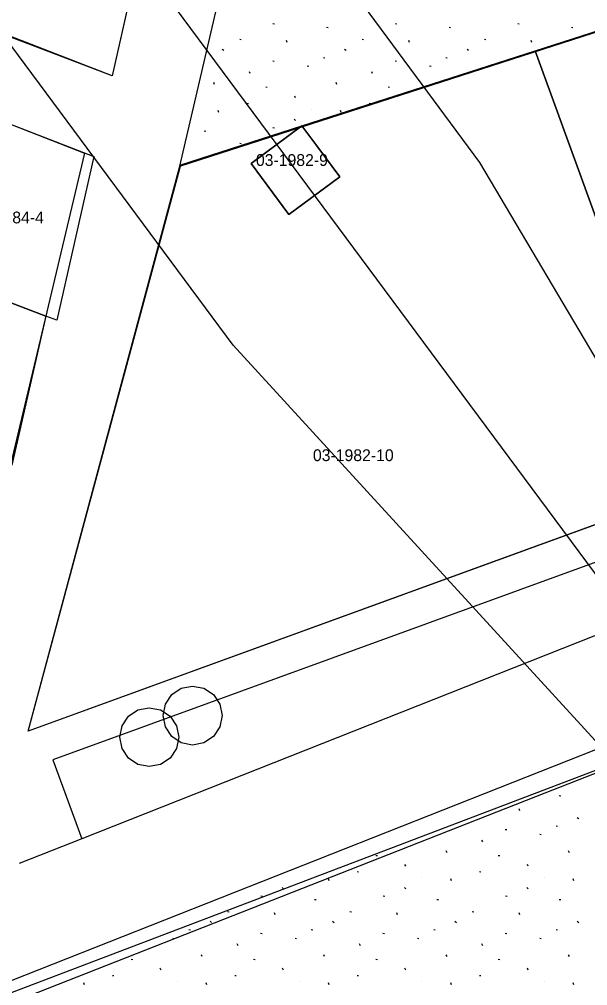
# Model space of a CAD drawing. Extents: x 413946 to 415528, y 4453939 to 4454944.
# Drawn here: x 414023.8 to 414071.9, y 4454810.9 to 4454892.9 of the extents above; entities that cross this region are included whole.
import ezdxf

# ---------------------------------------------------------------- set-up
doc = ezdxf.new("R2010")
doc.units = 0
for name, color, linetype in [('0_KADASTRO', 7, 'Continuous'), ('HAT_ENERJI_NAKIL_HAT', 7, 'Continuous'), ('KST_ENERJI_NAKIL_HAT', 7, 'Continuous'), ('Level 27', 7, 'Continuous'), ('Level 28', 7, 'Continuous'), ('Level 29', 7, 'Continuous'), ('Level 41', 7, 'Continuous'), ('Level 54', 7, 'Continuous'), ('Level 62', 7, 'Continuous'), ('SNR_FONKSIYON', 7, 'Continuous')]:
    doc.layers.add(name, color=color, linetype=linetype)

msp = doc.modelspace()

# ---------------------------------------------------------------- linework, layer by layer
at = {"layer": '0_KADASTRO'}
for points in [[(414020.97, 4454892.22), (414021.31, 4454893.14), (414023.89, 4454900.29), (414026, 4454905.75), (414030.78, 4454921.5), (414033.2, 4454920.77), (414038.65, 4454919.17), (414037.64, 4454914.76), (414031.62, 4454888.06), (414022.41, 4454891.66)], [(414067.47, 4454890.2), (414112.978, 4454904.868), (414125.885, 4454869.418), (414080.98, 4454853.07)], [(414024.52, 4454832.51), (414037.44, 4454880.52), (414047.72, 4454883.84), (414043.4, 4454880.63), (414046.6, 4454876.31), (414050.93, 4454879.51), (414048.98, 4454882.14), (414047.72, 4454883.84), (414067.47, 4454890.2), (414080.98, 4454853.07)], [(414017.66, 4454870.9), (414018.7, 4454873.47), (414022.51, 4454884.18), (414030.08, 4454881.22), (414026.94, 4454867.35), (414026.009, 4454867.706)], [(414043.4, 4454880.63), (414047.72, 4454883.84), (414048.98, 4454882.14), (414050.93, 4454879.51), (414046.6, 4454876.31)], [(414005.69, 4454860.71), (414009.57, 4454869.91), (414010.56, 4454873.54), (414017.66, 4454870.9), (414026.009, 4454867.706), (414023.14, 4454855.05)], [(414008.02, 4454803.57), (414068.33, 4454827.27), (414083.68, 4454833.3), (414088.17, 4454830.9), (414106.37, 4454805.76), (414106.62, 4454802.77), (414104.47, 4454806.16), (414101.1, 4454804.02), (414103.24, 4454800.64), (414106.62, 4454802.77), (414103.28, 4454796.68), (414079.29, 4454753.02)]]:
    msp.add_lwpolyline(points, close=True, dxfattribs=at)
at = {"layer": 'HAT_ENERJI_NAKIL_HAT'}
msp.add_lwpolyline([(414658.516, 4453939.478), (414647.224, 4454070.234), (413999.883, 4454943.957)], dxfattribs=at)
at = {"layer": 'KST_ENERJI_NAKIL_HAT'}
for p, q in [((414041.874, 4454865.239), (413983.573, 4454943.957)), ((414036.749, 4454915.966), (414062.768, 4454880.714)), ((414062.768, 4454880.714), (414107.065, 4454805.782)), ((414100.636, 4454801.021), (414041.874, 4454865.239))]:
    msp.add_line(p, q, dxfattribs=at)
at = {"layer": 'Level 27'}
for p, q in [((414038.65, 4454919.17), (414031.62, 4454888.06)), ((414031.62, 4454888.06), (414020.773, 4454892.194)), ((414022.51, 4454884.18), (414029.299, 4454881.525))]:
    msp.add_line(p, q, dxfattribs=at)
at = {"layer": 'Level 28'}
for p, q in [((414037.376, 4454880.414), (414044.828, 4454912.566)), ((414235.366, 4454909.281), (414024.523, 4454832.51)), ((414024.523, 4454832.51), (414037.376, 4454880.414)), ((414005.358, 4454803.615), (414085.768, 4454834.218))]:
    msp.add_line(p, q, dxfattribs=at)
at = {"layer": 'Level 29'}
msp.add_line((414029.299, 4454881.525), (414023.017, 4454855.088), dxfattribs=at)
at = {"layer": 'Level 41'}
for p, q in [((414045.262, 4454892.493), (414045.388, 4454892.469)), ((414045.262, 4454892.493), (414045.388, 4454892.469)), ((414055.63, 4454892.493), (414055.756, 4454892.469)), ((414055.63, 4454892.493), (414055.756, 4454892.469)), ((414065.998, 4454892.493), (414066.124, 4454892.469)), ((414065.998, 4454892.493), (414066.124, 4454892.469)), ((414049.81, 4454892.199), (414049.936, 4454892.176)), ((414049.81, 4454892.199), (414049.936, 4454892.176)), ((414060.178, 4454892.199), (414060.304, 4454892.176)), ((414060.178, 4454892.199), (414060.304, 4454892.176)), ((414070.546, 4454892.199), (414070.672, 4454892.176)), ((414070.546, 4454892.199), (414070.672, 4454892.176)), ((414042.442, 4454891.175), (414042.567, 4454891.15)), ((414042.442, 4454891.175), (414042.567, 4454891.15)), ((414046.475, 4454890.895), (414046.41, 4454891.058)), ((414046.475, 4454890.895), (414046.41, 4454891.058)), ((414052.81, 4454891.175), (414052.935, 4454891.15)), ((414052.81, 4454891.175), (414052.935, 4454891.15)), ((414056.843, 4454890.895), (414056.778, 4454891.058)), ((414056.843, 4454890.895), (414056.778, 4454891.058)), ((414063.178, 4454891.175), (414063.303, 4454891.15)), ((414063.178, 4454891.175), (414063.303, 4454891.15)), ((414067.211, 4454890.895), (414067.146, 4454891.058)), ((414067.211, 4454890.895), (414067.146, 4454891.058)), ((414040.967, 4454890.337), (414041.094, 4454890.238)), ((414040.967, 4454890.337), (414041.094, 4454890.238)), ((414051.335, 4454890.337), (414051.462, 4454890.238)), ((414051.335, 4454890.337), (414051.462, 4454890.238)), ((414061.703, 4454890.337), (414061.83, 4454890.238)), ((414061.703, 4454890.337), (414061.83, 4454890.238)), ((414045.235, 4454889.327), (414045.361, 4454889.304)), ((414045.235, 4454889.327), (414045.361, 4454889.304)), ((414049.54, 4454889.631), (414049.666, 4454889.608)), ((414049.54, 4454889.631), (414049.666, 4454889.608)), ((414055.603, 4454889.327), (414055.729, 4454889.304)), ((414055.603, 4454889.327), (414055.729, 4454889.304)), ((414059.908, 4454889.631), (414060.034, 4454889.608)), ((414059.908, 4454889.631), (414060.034, 4454889.608)), ((414043.332, 4454888.258), (414043.266, 4454888.421)), ((414043.332, 4454888.258), (414043.266, 4454888.421)), ((414048.164, 4454888.918), (414048.29, 4454888.893)), ((414048.164, 4454888.918), (414048.29, 4454888.893)), ((414053.7, 4454888.258), (414053.634, 4454888.421)), ((414053.7, 4454888.258), (414053.634, 4454888.421)), ((414058.532, 4454888.918), (414058.658, 4454888.893)), ((414058.532, 4454888.918), (414058.658, 4454888.893)), ((414040.301, 4454887.344), (414040.236, 4454887.507)), ((414040.301, 4454887.344), (414040.236, 4454887.507)), ((414050.669, 4454887.344), (414050.604, 4454887.507)), ((414050.669, 4454887.344), (414050.604, 4454887.507)), ((414044.65, 4454887.123), (414044.777, 4454887.1)), ((414044.65, 4454887.123), (414044.777, 4454887.1)), ((414055.018, 4454887.123), (414055.145, 4454887.1)), ((414055.018, 4454887.123), (414055.145, 4454887.1)), ((414047.173, 4454886.195), (414047.109, 4454886.356)), ((414047.173, 4454886.195), (414047.109, 4454886.356)), ((414040.682, 4454884.961), (414040.617, 4454885.123)), ((414040.682, 4454884.961), (414040.617, 4454885.123)), ((414043.047, 4454885.756), (414043.173, 4454885.731)), ((414043.047, 4454885.756), (414043.173, 4454885.731)), ((414048.531, 4454885.231), (414048.539, 4454885.229)), ((414048.531, 4454885.231), (414048.539, 4454885.229)), ((414051.05, 4454884.961), (414050.985, 4454885.123)), ((414051.05, 4454884.961), (414050.985, 4454885.123)), ((414053.415, 4454885.756), (414053.541, 4454885.731)), ((414053.415, 4454885.756), (414053.541, 4454885.731)), ((414047.056, 4454884.392), (414047.183, 4454884.294)), ((414047.056, 4454884.392), (414047.183, 4454884.294)), ((414045.262, 4454883.687), (414045.388, 4454883.663)), ((414045.262, 4454883.687), (414045.388, 4454883.663)), ((414039.442, 4454883.393), (414039.568, 4454883.37)), ((414039.442, 4454883.393), (414039.568, 4454883.37)), ((414042.442, 4454882.369), (414042.567, 4454882.344)), ((414042.442, 4454882.369), (414042.567, 4454882.344)), ((414069.517, 4454827.055), (414069.643, 4454827.032)), ((414069.517, 4454827.055), (414069.643, 4454827.032)), ((414066.182, 4454825.752), (414066.117, 4454825.914)), ((414066.182, 4454825.752), (414066.117, 4454825.914)), ((414069.247, 4454824.487), (414069.373, 4454824.464)), ((414069.247, 4454824.487), (414069.373, 4454824.464)), ((414071.042, 4454825.193), (414071.169, 4454825.094)), ((414071.042, 4454825.193), (414071.169, 4454825.094)), ((414064.942, 4454824.183), (414065.068, 4454824.16)), ((414064.942, 4454824.183), (414065.068, 4454824.16)), ((414067.871, 4454823.774), (414067.998, 4454823.749)), ((414067.871, 4454823.774), (414067.998, 4454823.749)), ((414063.039, 4454823.114), (414062.973, 4454823.277)), ((414063.039, 4454823.114), (414062.973, 4454823.277)), ((414053.99, 4454821.979), (414054.116, 4454821.956)), ((414053.99, 4454821.979), (414054.116, 4454821.956)), ((414060.008, 4454822.2), (414059.943, 4454822.363)), ((414060.008, 4454822.2), (414059.943, 4454822.363)), ((414064.358, 4454821.979), (414064.484, 4454821.956)), ((414064.358, 4454821.979), (414064.484, 4454821.956)), ((414070.376, 4454822.2), (414070.311, 4454822.363)), ((414070.376, 4454822.2), (414070.311, 4454822.363)), ((414056.512, 4454821.051), (414056.448, 4454821.212)), ((414056.512, 4454821.051), (414056.448, 4454821.212)), ((414066.88, 4454821.051), (414066.816, 4454821.212)), ((414066.88, 4454821.051), (414066.816, 4454821.212)), ((414052.386, 4454820.612), (414052.512, 4454820.587)), ((414052.386, 4454820.612), (414052.512, 4454820.587)), ((414062.754, 4454820.612), (414062.88, 4454820.587)), ((414062.754, 4454820.612), (414062.88, 4454820.587)), ((414050.021, 4454819.817), (414049.956, 4454819.98)), ((414050.021, 4454819.817), (414049.956, 4454819.98)), ((414057.87, 4454820.087), (414057.878, 4454820.085)), ((414057.87, 4454820.087), (414057.878, 4454820.085)), ((414060.389, 4454819.817), (414060.324, 4454819.98)), ((414060.389, 4454819.817), (414060.324, 4454819.98)), ((414068.238, 4454820.087), (414068.246, 4454820.085)), ((414068.238, 4454820.087), (414068.246, 4454820.085)), ((414070.757, 4454819.817), (414070.692, 4454819.98)), ((414070.757, 4454819.817), (414070.692, 4454819.98)), ((414046.027, 4454819.248), (414046.154, 4454819.15)), ((414046.027, 4454819.248), (414046.154, 4454819.15)), ((414056.395, 4454819.248), (414056.522, 4454819.15)), ((414056.395, 4454819.248), (414056.522, 4454819.15)), ((414066.763, 4454819.248), (414066.89, 4454819.15)), ((414066.763, 4454819.248), (414066.89, 4454819.15)), ((414044.233, 4454818.543), (414044.359, 4454818.519)), ((414044.233, 4454818.543), (414044.359, 4454818.519)), ((414048.781, 4454818.249), (414048.907, 4454818.226)), ((414048.781, 4454818.249), (414048.907, 4454818.226)), ((414054.601, 4454818.543), (414054.727, 4454818.519)), ((414054.601, 4454818.543), (414054.727, 4454818.519)), ((414059.149, 4454818.249), (414059.275, 4454818.226)), ((414059.149, 4454818.249), (414059.275, 4454818.226)), ((414064.969, 4454818.543), (414065.095, 4454818.519)), ((414064.969, 4454818.543), (414065.095, 4454818.519)), ((414069.517, 4454818.249), (414069.643, 4454818.226)), ((414069.517, 4454818.249), (414069.643, 4454818.226)), ((414041.413, 4454817.225), (414041.538, 4454817.2)), ((414041.413, 4454817.225), (414041.538, 4454817.2)), ((414045.446, 4454816.946), (414045.381, 4454817.108)), ((414045.446, 4454816.946), (414045.381, 4454817.108)), ((414051.781, 4454817.225), (414051.906, 4454817.2)), ((414051.781, 4454817.225), (414051.906, 4454817.2)), ((414055.814, 4454816.946), (414055.749, 4454817.108)), ((414055.814, 4454816.946), (414055.749, 4454817.108)), ((414062.149, 4454817.225), (414062.274, 4454817.2)), ((414062.149, 4454817.225), (414062.274, 4454817.2)), ((414066.182, 4454816.946), (414066.117, 4454817.108)), ((414066.182, 4454816.946), (414066.117, 4454817.108)), ((414039.938, 4454816.387), (414040.065, 4454816.288)), ((414039.938, 4454816.387), (414040.065, 4454816.288)), ((414050.306, 4454816.387), (414050.433, 4454816.288)), ((414050.306, 4454816.387), (414050.433, 4454816.288)), ((414060.674, 4454816.387), (414060.801, 4454816.288)), ((414060.674, 4454816.387), (414060.801, 4454816.288)), ((414071.042, 4454816.387), (414071.169, 4454816.288)), ((414071.042, 4454816.387), (414071.169, 4454816.288)), ((414038.143, 4454815.681), (414038.269, 4454815.658)), ((414038.143, 4454815.681), (414038.269, 4454815.658)), ((414048.511, 4454815.681), (414048.637, 4454815.658)), ((414048.511, 4454815.681), (414048.637, 4454815.658)), ((414058.879, 4454815.681), (414059.005, 4454815.658)), ((414058.879, 4454815.681), (414059.005, 4454815.658)), ((414069.247, 4454815.681), (414069.373, 4454815.658)), ((414069.247, 4454815.681), (414069.373, 4454815.658)), ((414036.767, 4454814.968), (414036.894, 4454814.943)), ((414036.767, 4454814.968), (414036.894, 4454814.943)), ((414044.206, 4454815.377), (414044.332, 4454815.354)), ((414044.206, 4454815.377), (414044.332, 4454815.354)), ((414047.135, 4454814.968), (414047.262, 4454814.943)), ((414047.135, 4454814.968), (414047.262, 4454814.943)), ((414054.574, 4454815.377), (414054.7, 4454815.354)), ((414054.574, 4454815.377), (414054.7, 4454815.354)), ((414057.503, 4454814.968), (414057.63, 4454814.943)), ((414057.503, 4454814.968), (414057.63, 4454814.943)), ((414064.942, 4454815.377), (414065.068, 4454815.354)), ((414064.942, 4454815.377), (414065.068, 4454815.354)), ((414067.871, 4454814.968), (414067.998, 4454814.943)), ((414067.871, 4454814.968), (414067.998, 4454814.943)), ((414042.303, 4454814.308), (414042.237, 4454814.471)), ((414042.303, 4454814.308), (414042.237, 4454814.471)), ((414052.671, 4454814.308), (414052.605, 4454814.471)), ((414052.671, 4454814.308), (414052.605, 4454814.471)), ((414063.039, 4454814.308), (414062.973, 4454814.471)), ((414063.039, 4454814.308), (414062.973, 4454814.471)), ((414033.254, 4454813.173), (414033.38, 4454813.15)), ((414033.254, 4454813.173), (414033.38, 4454813.15)), ((414039.272, 4454813.394), (414039.207, 4454813.557)), ((414039.272, 4454813.394), (414039.207, 4454813.557)), ((414043.622, 4454813.173), (414043.748, 4454813.15)), ((414043.622, 4454813.173), (414043.748, 4454813.15)), ((414049.64, 4454813.394), (414049.575, 4454813.557)), ((414049.64, 4454813.394), (414049.575, 4454813.557)), ((414053.99, 4454813.173), (414054.116, 4454813.15)), ((414053.99, 4454813.173), (414054.116, 4454813.15)), ((414060.008, 4454813.394), (414059.943, 4454813.557)), ((414060.008, 4454813.394), (414059.943, 4454813.557)), ((414064.358, 4454813.173), (414064.484, 4454813.15)), ((414064.358, 4454813.173), (414064.484, 4454813.15)), ((414070.376, 4454813.394), (414070.311, 4454813.557)), ((414070.376, 4454813.394), (414070.311, 4454813.557)), ((414035.776, 4454812.245), (414035.712, 4454812.406)), ((414035.776, 4454812.245), (414035.712, 4454812.406)), ((414046.144, 4454812.245), (414046.08, 4454812.406)), ((414046.144, 4454812.245), (414046.08, 4454812.406)), ((414056.512, 4454812.245), (414056.448, 4454812.406)), ((414056.512, 4454812.245), (414056.448, 4454812.406)), ((414066.88, 4454812.245), (414066.816, 4454812.406)), ((414066.88, 4454812.245), (414066.816, 4454812.406)), ((414031.65, 4454811.806), (414031.776, 4454811.781)), ((414031.65, 4454811.806), (414031.776, 4454811.781)), ((414042.018, 4454811.806), (414042.144, 4454811.781)), ((414042.018, 4454811.806), (414042.144, 4454811.781)), ((414052.386, 4454811.806), (414052.512, 4454811.781)), ((414052.386, 4454811.806), (414052.512, 4454811.781)), ((414062.754, 4454811.806), (414062.88, 4454811.781)), ((414062.754, 4454811.806), (414062.88, 4454811.781)), ((414026.766, 4454811.281), (414026.774, 4454811.279)), ((414026.766, 4454811.281), (414026.774, 4454811.279)), ((414029.285, 4454811.011), (414029.22, 4454811.174)), ((414029.285, 4454811.011), (414029.22, 4454811.174)), ((414037.134, 4454811.281), (414037.142, 4454811.279)), ((414037.134, 4454811.281), (414037.142, 4454811.279)), ((414039.653, 4454811.011), (414039.588, 4454811.174)), ((414039.653, 4454811.011), (414039.588, 4454811.174)), ((414047.502, 4454811.281), (414047.51, 4454811.279)), ((414047.502, 4454811.281), (414047.51, 4454811.279)), ((414050.021, 4454811.011), (414049.956, 4454811.174)), ((414050.021, 4454811.011), (414049.956, 4454811.174)), ((414057.87, 4454811.281), (414057.878, 4454811.279)), ((414057.87, 4454811.281), (414057.878, 4454811.279)), ((414060.389, 4454811.011), (414060.324, 4454811.174)), ((414060.389, 4454811.011), (414060.324, 4454811.174)), ((414068.238, 4454811.281), (414068.246, 4454811.279)), ((414068.238, 4454811.281), (414068.246, 4454811.279)), ((414070.757, 4454811.011), (414070.692, 4454811.174)), ((414070.757, 4454811.011), (414070.692, 4454811.174))]:
    msp.add_line(p, q, dxfattribs=at)
at = {"layer": 'Level 54'}
for points in [[(414235.366, 4454909.281), (414024.523, 4454832.51), (414037.376, 4454880.414), (414193.464, 4454930.784), (414203.673, 4454926.215), (414235.49, 4454913.3)], [(414038.65, 4454919.17), (414031.62, 4454888.06), (414020.773, 4454892.194), (414011.73, 4454895.64), (414002.61, 4454899), (414008.44, 4454912.68), (414014.22, 4454926.47), (414022.27, 4454924.05), (414030.78, 4454921.5)], [(414007.46, 4454889.72), (414014.99, 4454886.89), (414018.8, 4454885.66), (414022.51, 4454884.18), (414029.299, 4454881.525), (414023.017, 4454855.088), (414005.69, 4454860.71), (413997.39, 4454864.04), (413996.97, 4454863.1), (413988.28, 4454865.76), (413994.14, 4454879.51), (413999.47, 4454892.62)]]:
    msp.add_lwpolyline(points, close=True, dxfattribs=at)
at = {"layer": 'Level 62'}
for p, q in [((414096.802, 4454850.186), (414029.052, 4454823.393)), ((414100.085, 4454841.806), (414009.342, 4454805.921)), ((414036.682, 4454835.604), (414037.493, 4454836.146)), ((414037.493, 4454836.146), (414038.45, 4454836.336)), ((414038.45, 4454836.336), (414039.407, 4454836.146)), ((414039.407, 4454836.146), (414040.218, 4454835.604)), ((414036.14, 4454834.793), (414036.682, 4454835.604)), ((414040.218, 4454835.604), (414040.76, 4454834.793)), ((414033.009, 4454833.768), (414033.82, 4454834.31)), ((414033.82, 4454834.31), (414034.777, 4454834.5)), ((414034.777, 4454834.5), (414035.734, 4454834.31)), ((414035.734, 4454834.31), (414036.545, 4454833.768)), ((414035.95, 4454833.836), (414036.14, 4454834.793)), ((414040.76, 4454834.793), (414040.95, 4454833.836)), ((414032.467, 4454832.957), (414033.009, 4454833.768)), ((414036.14, 4454832.88), (414035.95, 4454833.836)), ((414036.545, 4454833.768), (414037.087, 4454832.957)), ((414040.95, 4454833.836), (414040.76, 4454832.88)), ((414032.277, 4454832), (414032.467, 4454832.957)), ((414036.682, 4454832.069), (414036.14, 4454832.88)), ((414037.087, 4454832.957), (414037.277, 4454832)), ((414040.76, 4454832.88), (414040.218, 4454832.069)), ((414032.467, 4454831.043), (414032.277, 4454832)), ((414037.493, 4454831.527), (414036.682, 4454832.069)), ((414037.277, 4454832), (414037.087, 4454831.043)), ((414040.218, 4454832.069), (414039.407, 4454831.527)), ((414033.009, 4454830.232), (414032.467, 4454831.043)), ((414037.087, 4454831.043), (414036.545, 4454830.232)), ((414038.45, 4454831.336), (414037.493, 4454831.527)), ((414039.407, 4454831.527), (414038.45, 4454831.336)), ((414033.82, 4454829.69), (414033.009, 4454830.232)), ((414036.545, 4454830.232), (414035.734, 4454829.69)), ((414026.617, 4454830.08), (414029.052, 4454823.393)), ((414034.777, 4454829.5), (414033.82, 4454829.69)), ((414035.734, 4454829.69), (414034.777, 4454829.5)), ((414029.052, 4454823.393), (414023.766, 4454821.303))]:
    msp.add_line(p, q, dxfattribs=at)
msp.add_lwpolyline([(414129.599, 4454867.578), (414026.617, 4454830.08)], dxfattribs=at)
at = {"layer": 'SNR_FONKSIYON'}
msp.add_line((414037.376, 4454880.414), (414193.464, 4454930.784), dxfattribs=at)

# ---------------------------------------------------------------- texts
at = {"layer": '0_KADASTRO'}
for s, p in [('03-1982-9', (414043.817, 4454880.429)), ('03-1984-4', (414019.748, 4454875.56)), ('03-1982-10', (414048.647, 4454855.404))]:
    msp.add_text(s, height=1, dxfattribs=at).set_placement(p)

doc.saveas('drawing.dxf')
